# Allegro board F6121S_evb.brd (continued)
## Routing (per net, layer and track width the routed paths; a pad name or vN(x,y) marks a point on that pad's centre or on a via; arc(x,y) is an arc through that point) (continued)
VDD: length 36.4
  TOP w0.305: U3.E5 v2(48.75,41.4) U3.E4 48.5,41.4 ; U3.E3 v2(48.24,41.4) 48.5,41.4 ; 48.5,41.4 v2(48.5,41.13) 48.5,41.13 U3.F4
  TOP w0.508: C6.2 49.35,46.8 50.15,47.6 C20.2 v6(50.93,47.94) ; J16.2 C1.2 C4.2 C3.2 ; C7.2 C5.2
  L2 w0.254: J16.2 26.14,81.34 ; J16.2 25.19,80.39 ; J16.2 26.14,79.44 ; J16.2 27.1,80.39 ; 40.11,54.69 TP6.1 ; TP6.1 38.92,55.88 ; TP6.1 40.11,57.07 ; TP6.1 41.31,55.88 ; J16.8 19.48,80.39 ; J16.8 18.52,81.34 ; J16.8 17.57,80.39 ; J16.8 18.52,79.44 ; 15.03,80.39 J16.10 ; J16.10 16.94,80.39 ; J16.10 15.98,81.34 ; J16.10 15.98,79.44 ; 23.6,79.44 J16.4 ; J16.4 24.56,80.39 ; J16.4 23.6,81.34 ; J16.4 22.65,80.39 ; J16.6 21.06,81.34 ; J16.6 22.02,80.39 ; J16.6 20.11,80.39 ; J16.6 21.06,79.44
  BOTTOM w0.254: 50.1,42.26 C18.2 ; C18.2 50.1,41.5 ; C18.2 50.86,42.26 ; C19.2 46.13,42.11 ; C19.2 45.59,41.57 ; C19.2 46.68,41.57
  vias: v6(41.33,48.84) v6(41.33,48.49) v6(41.33,48.13) v6(41.33,47.78) v6(41.33,47.42) v6(41.33,47.07) v6(41.33,46.71) v6(41.69,48.84) v6(41.69,48.49) v6(41.69,48.13) v6(41.69,47.78) v6(41.69,47.42) v6(41.69,47.07) v6(41.69,46.71) v6(42.05,48.84) v6(42.05,48.49) v6(42.05,48.13) v6(42.05,47.78) v6(42.05,47.42) v6(42.05,47.07) v6(42.05,46.71) v6(42.4,48.84) v6(42.4,48.49) v6(42.4,48.13) v6(42.4,47.78) v6(42.4,47.42) v6(42.4,47.07) v6(42.4,46.71) v6(42.76,48.84) v6(42.76,48.49) v6(42.76,48.13) v6(42.76,47.78) v6(42.76,47.42) v6(42.76,47.07) v6(42.76,46.71) v6(43.11,48.82) v6(43.11,48.46) v6(43.11,48.11) v6(43.11,47.75) v6(43.11,47.4) v6(43.11,47.04) v6(43.11,46.69) v6(43.47,48.82) v6(43.47,48.46) v6(43.47,48.11) v6(43.47,47.75) v6(43.47,47.4) v6(43.47,47.04) v6(43.47,46.69) v6(44.94,46.94) v6(45.22,46.66) v6(45.63,46.81) v6(46,46.95) v6(46.32,46.65) v6(49.11,46.96) v6(49.41,46.66) v6(50,48.06) v6(50.3,47.8) v6(50.71,47.04) v6(50.71,46.69) v6(51.09,49.17) v6(51.09,48.82) v6(51.09,48.46) v6(51.06,47.4) v6(51.06,47.04) v6(51.06,46.69) v6(51.44,49.17) v6(51.44,48.82) v6(51.44,48.46) v6(51.44,48.11) v6(51.44,47.75) v6(51.42,47.4) v6(51.42,47.04) v6(51.42,46.69) v6(51.8,49.17) v6(51.8,48.82) v6(51.8,48.46) v6(51.8,48.08) v6(51.8,47.73) v6(51.77,47.37) v6(51.77,47.02) v6(51.77,46.66) v6(52.13,47.4) v6(52.13,47.04) v6(52.13,46.69) v6(52.15,49.17) v6(52.15,48.82) v6(52.15,48.46) v6(52.15,48.11) v6(52.15,47.75)
VDD_CREG: length 51.8
  TOP w0.305: TP4.1 47.23,53.85 R20.2
  TOP w0.508: J15.3 J14.1 J13.1 J12.1 40.1,77.99 C8.2 37.69,77.98 J11.3
  BOTTOM w0.508: J11.3 35.87,65.2 TP4.1
ADD1: length 59.4
  BOTTOM w0.127: v6(49,40.4) 47.69,39.09 40.39,39.09 30.08,49.4 30.08,78.41 30.89,79.22 34.58,79.22 J11.2
ADD2: length 70.2
  BOTTOM w0.127: v6(49,40.9) 49.41,40.49 49.41,39.98 46.9,37.47 41.27,37.47 29.56,49.18 29.56,81.14 30.23,81.81 38.82,81.81 J12.2
ADD3: length 46.4
  BOTTOM w0.127: v6(49,41.9) 48.4,42.5 48.4,74.8 50.1,76.5 50.1,80.9 49.28,81.71 45.63,81.71 J13.2
ADD4: length 39.4
  BOTTOM w0.127: J14.2 47.48,79.25 47.48,76.12 48,75.61 v6(48,41.9)
ADD5: length 40.9
  L3 w0.127: v6(48.74,49) 47.98,49 47.55,48.57 47.55,46.58 48,46.13 v3(48,42.4)
  BOTTOM w0.127: J15.2 50.51,78.22 50.51,76.28 48.74,74.51 v6(48.74,49)
CREG: length 6.2
  TOP w0.254: U3.C4 v4(48.5,42.14) U3.D4
  TOP w0.305: R20.1 48.2,46.7 v3(48.24,46.66)
  L3 w0.305: v4(48.5,42.14) 48.5,46.41 v3(48.24,46.66)
CSB: length 55.8
  TOP w0.127: v1(69.58,76.78) R12.2 R13.2 ; U3.B4 v5(48.24,42.91)
  TOP w0.254: U3.B4 U3.B3
  L2 w0.127: v5(48.24,42.91) 48.24,43.15 50.83,45.74 53.16,45.74 53.7,46.29 53.7,49.53 52.74,50.5 52.74,72.95 57.67,77.88 68.48,77.88 v1(69.58,76.78)
F2232H_CSB: length 2.6
  TOP w0.127: J22.12 69.58,78.99 R12.1
F2232H_RESET: length 2
  TOP w0.127: R10.1 J22.8
F2232H_SCLK: length 2
  TOP w0.127: R14.1 J22.16
RESET: length 52.8
  TOP w0.127: U3.A3 48,43.72 50.5,46.23 53.96,46.23 55.08,47.35 55.08,54.25 63.3,62.48 v6(63.3,76.02) ; R11.2 R10.2 v6(73.13,76.84)
  BOTTOM w0.127: v6(73.13,76.84) 72.32,76.02 v6(63.3,76.02)
RF1: length 46.2
  L2 w0.203: v1(47,42.9) 45.17,42.9 arc(42.8,43.37) 40.79,44.72 19.22,66.28 arc(18.08,67.04) 16.74,67.31 v1(10.47,67.31)
RF2: length 46.2
  L2 w0.203: v1(3.5,50.04) 25.74,50.04 arc(28.17,49.55) 30.23,48.18 33.89,44.51 arc(36.78,42.58) 40.19,41.9 v1(47,41.9)
RF3: length 46.2
  L2 w0.203: v1(3.5,32.77) 25.74,32.77 arc(28.17,33.25) 30.23,34.63 33.89,38.29 arc(36.78,40.22) 40.19,40.9 v1(47,40.9)
RF4: length 46.2
  L2 w0.203: v1(47,39.9) 45.17,39.9 arc(42.8,39.43) 40.79,38.09 19.22,16.52 arc(18.08,15.76) 16.74,15.49 v1(10.47,15.49)
RF5: length 46.2
  L2 w0.203: v1(50,39.9) 51.83,39.9 arc(54.2,39.43) 56.2,38.09 77.77,16.52 arc(78.91,15.76) 80.25,15.49 v1(86.52,15.49)
RF6: length 46.2
  L2 w0.203: v1(93.49,32.77) 71.26,32.77 arc(68.83,33.25) 66.77,34.63 63.1,38.29 arc(60.21,40.22) 56.8,40.9 v1(50,40.9)
RF7: length 46.2
  L2 w0.203: v1(93.49,50.04) 71.26,50.04 arc(68.83,49.55) 66.77,48.18 63.1,44.51 arc(60.21,42.58) 56.8,41.9 v1(50,41.9)
RF8: length 46.2
  L2 w0.203: v1(86.52,67.31) 80.25,67.31 arc(78.91,67.04) 77.77,66.28 56.2,44.72 arc(54.2,43.37) 51.83,42.9 v1(50,42.9)
SCLK: length 43.5
  TOP w0.127: R14.2 R15.2 63.99,62.33 55.61,53.95 55.61,47.37 54.16,45.92 50.71,45.92 48.5,43.71 U3.A4
SDI: length 43.1
  TOP w0.127: R17.2 R16.2 v6(59.42,76.82)
  TOP w0.254: U3.B5 v5(49,42.66) U3.C5
  L2 w0.127: v6(59.42,76.82) 58.36,76.82 53.37,71.83 53.37,50.62 53.96,50.04 53.96,46.1 53.32,45.47 50.99,45.47 49,43.48 v5(49,42.66)
SDO: length 43.2
  TOP w0.127: R18.2 66.28,75.74 64.65,74.12 64.65,62.18 56.12,53.64 56.12,47.37 54.34,45.59 50.88,45.59 49,43.71 U3.A5
TRIG: length 15.7
  TOP w0.203: 76.23,75.39 76.23,73.66 72.19,69.62 69.35,69.62 J30.1
  TOP w0.216: J22.6 76.23,79.96 76.23,75.39
N397655: length 39.7
  L2 w0.203: v1(58.66,3.5) 58.66,24.41 arc(58.43,25.54) 57.79,26.49 49.68,34.61 arc(49.17,35.36) 49,36.25 v1(49,39.4)
N397670: length 39.7
  L2 w0.203: v1(38.34,3.5) 38.34,24.41 arc(38.56,25.54) 39.2,26.49 47.32,34.61 arc(47.82,35.36) 48,36.25 v1(48,39.4)
N472884: length 1
  TOP w0.127: R11.1 75.14,78.52 C12.2
N475952: length 2.4
  TOP w0.127: J22.18 59.42,79.5 R16.1
N485360: length 3.3
  TOP w0.127: R19.2 66.3,78.55 R18.1 66.28,79.76 J22.14
N489259: length 2.6
  TOP w0.254: R21.1 31.52,80.56 J23.1
N510107: length 1
  TOP w0.127: C14.2 70.62,78.55 R13.1
N511327: length 1
  TOP w0.127: C17.2 68.11,77.46 R19.1
N512531: length 1
  TOP w0.127: R15.1 64.02,78.55 C15.2
N513256: length 1
  TOP w0.127: R17.1 61.43,78.52 C16.2
N546379: length 50.5
  TOP w0.254: U3.G3 v2(48,40.65) U3.F3
  BOTTOM w0.254: v2(48,40.65) 46.85,39.5 40.8,39.5 31.48,48.83 J23.2
N558773: length 1.2
  TOP w0.254: C20.1 50.15,50.13 R26.2

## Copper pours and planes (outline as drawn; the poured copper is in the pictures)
GND on TOP: 93.78,50.34 96.1,50.34 96.99,50.54 96.99,56.39 89.53,56.39 89.53,43.69 96.99,43.69 96.99,49.54 96.1,49.73 93.78,49.73 93.69,49.67 93.59,49.63 93.48,49.62 93.37,49.63 93.27,49.68 93.19,49.74 93.12,49.83 93.08,49.93 93.07,50.04 93.08,50.15 93.12,50.25 93.19,50.33 93.27,50.4 93.37,50.44 93.48,50.46 93.59,50.45 93.69,50.41
GND on TOP: 86.81,67.61 89.14,67.61 90.03,67.81 90.03,73.66 82.56,73.66 82.56,60.96 90.03,60.96 90.03,66.81 89.14,67.01 86.81,67.01 86.72,66.94 86.62,66.9 86.51,66.89 86.41,66.91 86.31,66.95 86.22,67.02 86.16,67.1 86.12,67.2 86.1,67.31 86.12,67.42 86.16,67.52 86.22,67.6 86.31,67.67 86.41,67.71 86.51,67.73 86.62,67.72 86.72,67.68
GND on TOP: 58.96,3.22 58.96,0.89 59.15,0 65.01,0 65.01,7.47 52.31,7.47 52.31,0 58.16,0 58.35,0.89 58.35,3.22 58.29,3.31 58.25,3.41 58.24,3.51 58.25,3.62 58.3,3.72 58.36,3.8 58.45,3.87 58.55,3.91 58.66,3.92 58.76,3.91 58.86,3.87 58.95,3.8 59.02,3.72 59.06,3.62 59.08,3.51 59.06,3.41 59.03,3.31
GND on TOP: 10.19,67.01 7.86,67.01 6.97,66.81 6.97,60.96 14.44,60.96 14.44,73.66 6.97,73.66 6.97,67.81 7.86,67.61 10.19,67.61 10.27,67.68 10.37,67.72 10.48,67.73 10.59,67.71 10.69,67.67 10.77,67.6 10.84,67.52 10.88,67.42 10.89,67.31 10.88,67.2 10.84,67.1 10.77,67.02 10.69,66.95 10.59,66.91 10.48,66.89 10.37,66.9 10.27,66.94
GND on TOP: 86.81,15.8 89.14,15.8 90.03,15.99 90.03,21.84 82.56,21.84 82.56,9.14 90.03,9.14 90.03,15 89.14,15.19 86.81,15.19 86.72,15.13 86.62,15.09 86.51,15.07 86.41,15.09 86.31,15.13 86.22,15.2 86.16,15.29 86.12,15.39 86.1,15.49 86.12,15.6 86.16,15.7 86.22,15.79 86.31,15.85 86.41,15.9 86.51,15.91 86.62,15.9 86.72,15.86
GND on TOP: 6.97,0 6.97,9.34 14.39,9.34 14.39,21.64 6.97,21.64 6.97,25.41 0,25.41 0,26.58 7.46,26.58 7.42,26.58 7.41,38.9 0,38.9 0,43.87 7.4,43.87 7.38,56.19 0,56.2 0,57.39 6.97,57.39 6.97,61.15 14.4,61.15 14.4,73.46 6.97,73.46 6.97,86.08 90.03,86.08 90.03,73.44 82.61,73.44 82.61,61.12 90.03,61.13 90.03,57.39 96.99,57.39 96.99,56.21 89.58,56.21 89.57,43.86 96.99,43.86 96.99,38.9 89.58,38.9 89.57,26.62 96.99,26.62 96.99,25.41 90.03,25.41 90.03,21.64 82.61,21.64 82.61,9.33 90.03,9.33 90.02,0 64.77,0 64.77,7.38 52.54,7.38 52.52,0 44.48,0 44.48,7.43 32.18,7.4 32.16,0 ; 2 cut-outs
GND on TOP: 3.22,49.73 0.89,49.73 0,49.54 0,43.69 7.47,43.69 7.47,56.39 0,56.39 0,50.54 0.89,50.34 3.22,50.34 3.31,50.41 3.41,50.45 3.51,50.46 3.62,50.44 3.72,50.4 3.8,50.33 3.87,50.25 3.91,50.15 3.92,50.04 3.91,49.93 3.87,49.83 3.8,49.74 3.72,49.68 3.62,49.63 3.51,49.62 3.41,49.63 3.31,49.67
GND on TOP: 93.78,33.07 96.1,33.07 96.99,33.26 96.99,39.12 89.53,39.12 89.53,26.42 96.99,26.42 96.99,32.27 96.1,32.46 93.78,32.46 93.69,32.4 93.59,32.36 93.48,32.35 93.37,32.36 93.27,32.41 93.19,32.47 93.12,32.56 93.08,32.66 93.07,32.77 93.08,32.87 93.12,32.97 93.19,33.06 93.27,33.13 93.37,33.17 93.48,33.19 93.59,33.17 93.69,33.13
GND on TOP: 10.19,15.19 7.86,15.19 6.97,15 6.97,9.14 14.44,9.14 14.44,21.84 6.97,21.84 6.97,15.99 7.86,15.8 10.19,15.8 10.27,15.86 10.37,15.9 10.48,15.91 10.59,15.9 10.69,15.85 10.77,15.79 10.84,15.7 10.88,15.6 10.89,15.49 10.88,15.39 10.84,15.29 10.77,15.2 10.69,15.13 10.59,15.09 10.48,15.07 10.37,15.09 10.27,15.13
GND on TOP: 3.22,32.46 0.89,32.46 0,32.27 0,26.42 7.47,26.42 7.47,39.12 0,39.12 0,33.26 0.89,33.07 3.22,33.07 3.31,33.13 3.41,33.17 3.51,33.19 3.62,33.17 3.72,33.13 3.8,33.06 3.87,32.97 3.91,32.87 3.92,32.77 3.91,32.66 3.87,32.56 3.8,32.47 3.72,32.41 3.62,32.36 3.51,32.35 3.41,32.36 3.31,32.4
GND on TOP: 38.64,3.22 38.64,0.89 38.83,0 44.69,0 44.69,7.47 31.99,7.47 31.99,0 37.84,0 38.03,0.89 38.03,3.22 37.97,3.31 37.93,3.41 37.92,3.51 37.93,3.62 37.98,3.72 38.04,3.8 38.13,3.87 38.23,3.91 38.34,3.92 38.44,3.91 38.54,3.87 38.63,3.8 38.7,3.72 38.74,3.62 38.76,3.51 38.74,3.41 38.71,3.31
GND on BOTTOM, L3: 6.97,25.41 0,25.41 0,57.39 6.97,57.39 6.97,86.08 90.03,86.08 90.03,57.39 96.99,57.39 96.99,25.41 90.03,25.41 90.03,0 6.97,0
GND on L2: 6.97,21.84 14.44,21.84 14.44,15.82 10.73,15.82 10.64,15.88 10.53,15.91 10.42,15.91 10.31,15.88 10.27,15.86 10.22,15.82 10.1,15.68 10.06,15.49 10.1,15.31 10.22,15.16 10.27,15.13 10.31,15.11 10.42,15.08 10.53,15.08 10.64,15.11 10.73,15.16 14.44,15.16 14.44,9.14 6.97,9.14
GND on L2: 82.56,21.84 90.03,21.84 90.03,9.14 82.56,9.14 82.56,15.16 86.26,15.16 86.31,15.13 86.41,15.09 86.63,15.09 86.73,15.13 86.77,15.16 86.9,15.31 86.94,15.49 86.9,15.68 86.77,15.83 86.73,15.86 86.63,15.9 86.41,15.9 86.31,15.85 86.26,15.82 82.56,15.82
GND on L2: 38.67,7.47 44.69,7.47 44.69,0 31.99,0 31.99,7.47 38.01,7.47 38.01,3.76 37.95,3.67 37.92,3.56 37.92,3.45 37.95,3.35 38,3.25 38.01,3.25 38.15,3.13 38.34,3.09 38.52,3.13 38.66,3.25 38.67,3.25 38.72,3.35 38.75,3.45 38.75,3.56 38.72,3.67 38.67,3.76
GND on L2: 6.97,73.66 14.44,73.66 14.44,67.64 10.73,67.64 10.68,67.67 10.58,67.71 10.37,67.71 10.26,67.67 10.22,67.64 10.1,67.5 10.05,67.31 10.1,67.12 10.22,66.98 10.26,66.95 10.37,66.91 10.58,66.91 10.68,66.95 10.73,66.98 14.44,66.98 14.44,60.96 6.97,60.96
GND on L2: 6.97,25.41 0,25.41 0,26.58 7.35,26.59 7.35,38.88 0,38.95 0,43.69 7.48,43.69 7.48,56.21 0,56.21 0,57.39 6.97,57.39 6.97,61.21 14.33,61.21 14.33,73.47 6.97,73.47 6.97,86.08 90.03,86.08 90.03,73.66 82.79,73.66 82.79,60.96 90.03,60.96 90.03,57.39 96.99,57.39 96.99,56.21 89.55,56.21 89.55,43.69 96.99,43.69 96.99,38.94 89.55,38.94 89.55,26.58 96.99,26.58 96.99,25.41 90.03,25.41 90.03,21.84 82.79,21.84 82.79,9.14 90.03,9.14 90.03,0 64.75,0 64.75,7.37 52.43,7.37 52.43,0 44.43,0 44.43,7.37 32.24,7.37 32.24,0 6.97,0 6.97,9.4 14.33,9.37 14.33,21.59 6.97,21.59 ; 10 cut-outs
GND on L2: 89.48,56.39 96.99,56.39 96.99,43.69 89.53,43.69 89.53,49.71 93.23,49.71 93.28,49.68 93.38,49.64 93.6,49.63 93.7,49.68 93.86,49.85 93.91,50.04 93.86,50.22 93.7,50.4 93.6,50.44 93.38,50.44 93.28,50.4 93.23,50.37 89.48,50.37
GND on L2: 89.53,39.12 96.99,39.12 96.99,26.42 89.53,26.42 89.53,32.44 93.23,32.44 93.28,32.41 93.38,32.36 93.6,32.36 93.7,32.4 93.74,32.43 93.86,32.58 93.91,32.77 93.86,32.95 93.74,33.1 93.7,33.13 93.6,33.17 93.38,33.17 93.28,33.13 93.23,33.1 89.53,33.1
GND on L2: 82.56,73.66 90.03,73.66 90.03,60.96 82.56,60.96 82.56,66.98 86.26,66.98 86.31,66.95 86.41,66.91 86.63,66.91 86.73,66.95 86.77,66.98 86.9,67.12 86.94,67.31 86.9,67.5 86.77,67.64 86.73,67.67 86.63,67.71 86.41,67.71 86.31,67.67 86.26,67.64 82.56,67.64
GND on L2: 0,39.12 7.47,39.12 7.47,33.1 3.76,33.1 3.67,33.15 3.56,33.18 3.45,33.18 3.35,33.15 3.3,33.13 3.25,33.1 3.13,32.95 3.09,32.77 3.13,32.58 3.25,32.44 3.3,32.4 3.35,32.38 3.45,32.35 3.56,32.35 3.67,32.38 3.76,32.44 7.47,32.44 7.47,26.42 0,26.42
GND on L2: 0,56.39 7.49,56.39 7.49,50.37 3.76,50.37 3.72,50.4 3.62,50.44 3.4,50.44 3.3,50.4 3.25,50.37 3.13,50.22 3.09,50.04 3.13,49.85 3.25,49.71 3.3,49.68 3.4,49.63 3.62,49.64 3.72,49.68 3.76,49.71 7.5,49.71 7.5,43.69 0,43.69
GND on L2: 58.99,7.47 65.01,7.47 65.01,0 52.31,0 52.31,7.47 58.33,7.47 58.33,3.76 58.27,3.67 58.25,3.62 58.24,3.5 58.25,3.4 58.29,3.3 58.33,3.25 58.47,3.13 58.66,3.09 58.84,3.13 58.99,3.25 59.02,3.3 59.06,3.4 59.07,3.5 59.06,3.62 59.04,3.67 58.99,3.76
VDD on BOTTOM: 48.73,49.39 52.56,49.39 52.56,43.43 50.33,41.2 50.33,40.56 49.72,40.56 49.18,41.2 48.86,41.2 48.69,41.02 48.7,40.69 46.74,40.69 46.74,41.22 42.55,41.22 41.12,42.65 41.09,49.35 47.63,49.35 47.63,41.81 47.85,41.59 49.14,41.58 49.31,41.74 49.31,42.14 48.73,42.72
VDD on L2: 27.9,81.66 13.98,81.66 13.98,77.51 18.04,77.55 18.04,71.48 35.42,54.1 41.11,54.08 41.11,46.36 52.56,46.36 52.56,49.53 48.09,49.53 48.09,63.7 27.9,77.19
RF1 on TOP (solid shape): 10.51,67.52 10.56,67.51 10.61,67.48 10.65,67.44 10.67,67.39 10.69,67.34 10.69,67.28 10.67,67.23 10.65,67.18 10.61,67.14 10.56,67.11 10.51,67.1 10.45,67.1 10.4,67.11 10.35,67.13 6.97,67.13 6.97,67.49 10.35,67.49 10.4,67.51 10.45,67.52
RF1 on L2 (solid shape): 10.52,67.45 10.56,67.44 10.59,67.41 14.44,67.41 14.44,67.21 10.59,67.21 10.56,67.18 10.52,67.17 10.49,67.16 10.45,67.16 10.41,67.17 10.38,67.19 10.35,67.22 10.33,67.25 10.32,67.29 10.32,67.33 10.33,67.37 10.35,67.4 10.38,67.43 10.41,67.45 10.45,67.46 10.49,67.46
RF2 on TOP (solid shape): 3.54,50.25 3.59,50.24 3.64,50.21 3.68,50.17 3.71,50.12 3.72,50.07 3.72,50.01 3.71,49.96 3.68,49.91 3.64,49.87 3.59,49.84 3.54,49.82 3.49,49.82 3.43,49.84 3.38,49.86 0,49.86 0,50.22 3.38,50.22 3.43,50.24 3.49,50.25
RF2 on L2 (solid shape): 3.55,50.18 3.59,50.16 3.62,50.14 7.47,50.14 7.47,49.94 3.62,49.94 3.59,49.91 3.55,49.89 3.52,49.89 3.48,49.89 3.44,49.9 3.41,49.92 3.38,49.95 3.36,49.98 3.35,50.02 3.35,50.06 3.36,50.09 3.38,50.13 3.41,50.16 3.44,50.18 3.48,50.19 3.52,50.19
RF3 on TOP (solid shape): 3.54,32.98 3.59,32.96 3.64,32.93 3.68,32.89 3.71,32.85 3.72,32.79 3.72,32.74 3.71,32.69 3.68,32.64 3.64,32.6 3.59,32.57 3.54,32.55 3.49,32.55 3.43,32.56 3.38,32.59 0,32.59 0,32.94 3.38,32.94 3.43,32.97 3.49,32.98
RF3 on L2 (solid shape): 3.55,32.91 3.59,32.89 3.62,32.87 7.47,32.87 7.47,32.66 3.62,32.66 3.59,32.64 3.55,32.62 3.52,32.61 3.48,32.62 3.44,32.63 3.41,32.65 3.38,32.68 3.36,32.71 3.35,32.75 3.35,32.79 3.36,32.82 3.38,32.86 3.41,32.88 3.44,32.9 3.48,32.92 3.52,32.92
RF4 on TOP (solid shape): 10.51,15.71 10.56,15.69 10.61,15.66 10.65,15.62 10.67,15.57 10.69,15.52 10.69,15.47 10.67,15.41 10.65,15.37 10.61,15.33 10.56,15.3 10.51,15.28 10.45,15.28 10.4,15.29 10.35,15.32 6.97,15.32 6.97,15.67 10.35,15.67 10.4,15.7 10.45,15.71
RF4 on L2 (solid shape): 10.52,15.64 10.56,15.62 10.59,15.6 14.44,15.6 14.44,15.39 10.59,15.39 10.56,15.37 10.52,15.35 10.49,15.34 10.45,15.34 10.41,15.36 10.38,15.38 10.35,15.4 10.33,15.44 10.32,15.47 10.32,15.51 10.33,15.55 10.35,15.58 10.38,15.61 10.41,15.63 10.45,15.64 10.49,15.65
RF5 on TOP (solid shape): 86.59,15.7 86.64,15.67 90.03,15.67 90.03,15.32 86.64,15.32 86.59,15.29 86.54,15.28 86.49,15.28 86.43,15.3 86.39,15.33 86.35,15.37 86.32,15.41 86.31,15.47 86.31,15.52 86.32,15.57 86.35,15.62 86.39,15.66 86.43,15.69 86.49,15.71 86.54,15.71
RF5 on L2 (solid shape): 86.55,15.64 86.58,15.63 86.62,15.61 86.64,15.58 86.66,15.55 86.67,15.51 86.67,15.47 86.66,15.44 86.64,15.4 86.62,15.38 86.58,15.36 86.55,15.34 86.51,15.34 86.47,15.35 86.44,15.37 86.41,15.39 82.56,15.39 82.56,15.6 86.41,15.6 86.44,15.62 86.47,15.64 86.51,15.65
RF6 on TOP (solid shape): 93.56,32.97 93.61,32.94 96.99,32.94 96.99,32.59 93.61,32.59 93.56,32.56 93.51,32.55 93.45,32.55 93.4,32.57 93.35,32.6 93.32,32.64 93.29,32.69 93.27,32.74 93.27,32.79 93.29,32.85 93.32,32.89 93.35,32.93 93.4,32.96 93.45,32.98 93.51,32.98
RF6 on L2 (solid shape): 93.51,32.92 93.55,32.9 93.58,32.88 93.61,32.86 93.63,32.82 93.64,32.79 93.64,32.75 93.63,32.71 93.61,32.68 93.58,32.65 93.55,32.63 93.51,32.62 93.48,32.61 93.44,32.62 93.4,32.64 93.37,32.66 89.53,32.66 89.53,32.87 93.37,32.87 93.4,32.89 93.44,32.91 93.48,32.92
RF7 on TOP (solid shape): 93.56,50.24 93.61,50.22 96.99,50.22 96.99,49.86 93.61,49.86 93.56,49.84 93.51,49.82 93.45,49.82 93.4,49.84 93.35,49.87 93.32,49.91 93.29,49.96 93.27,50.01 93.27,50.07 93.29,50.12 93.32,50.17 93.35,50.21 93.4,50.24 93.45,50.25 93.51,50.25
RF7 on L2 (solid shape): 93.51,50.19 93.55,50.18 93.58,50.16 93.61,50.13 93.63,50.09 93.64,50.06 93.64,50.02 93.63,49.98 93.61,49.95 93.58,49.92 93.55,49.9 93.51,49.89 93.48,49.89 93.44,49.89 93.4,49.91 93.37,49.94 89.53,49.94 89.53,50.14 93.37,50.14 93.4,50.16 93.44,50.18 93.48,50.19
RF8 on TOP (solid shape): 86.59,67.51 86.64,67.49 90.03,67.49 90.03,67.13 86.64,67.13 86.59,67.11 86.54,67.1 86.49,67.1 86.43,67.11 86.39,67.14 86.35,67.18 86.32,67.23 86.31,67.28 86.31,67.34 86.32,67.39 86.35,67.44 86.39,67.48 86.43,67.51 86.49,67.52 86.54,67.52
RF8 on L2 (solid shape): 86.55,67.46 86.58,67.45 86.62,67.43 86.64,67.4 86.66,67.37 86.67,67.33 86.67,67.29 86.66,67.25 86.64,67.22 86.62,67.19 86.58,67.17 86.55,67.16 86.51,67.16 86.47,67.17 86.44,67.18 86.41,67.21 82.56,67.21 82.56,67.41 86.41,67.41 86.44,67.44 86.47,67.45 86.51,67.46
N397655 on TOP (solid shape): 58.74,3.71 58.79,3.68 58.83,3.64 58.85,3.59 58.87,3.54 58.87,3.49 58.86,3.43 58.83,3.38 58.83,0 58.48,0 58.48,3.38 58.45,3.43 58.44,3.49 58.44,3.54 58.46,3.59 58.49,3.64 58.53,3.68 58.58,3.71 58.63,3.72 58.68,3.72
N397655 on L2 (solid shape): 58.76,3.62 58.78,3.59 58.8,3.55 58.81,3.52 58.81,3.48 58.8,3.44 58.78,3.41 58.75,3.38 58.71,3.36 58.68,3.35 58.64,3.35 58.6,3.36 58.57,3.38 58.54,3.41 58.52,3.44 58.51,3.48 58.5,3.52 58.51,3.55 58.53,3.59 58.56,3.62 58.56,7.47 58.76,7.47
N397670 on TOP (solid shape): 38.42,3.71 38.47,3.68 38.51,3.64 38.53,3.59 38.55,3.54 38.55,3.49 38.54,3.43 38.51,3.38 38.51,0 38.16,0 38.16,3.38 38.13,3.43 38.12,3.49 38.12,3.54 38.14,3.59 38.17,3.64 38.21,3.68 38.26,3.71 38.31,3.72 38.36,3.72
N397670 on L2 (solid shape): 38.44,3.62 38.46,3.59 38.48,3.55 38.49,3.52 38.49,3.48 38.48,3.44 38.46,3.41 38.43,3.38 38.39,3.36 38.36,3.35 38.32,3.35 38.28,3.36 38.25,3.38 38.22,3.41 38.2,3.44 38.19,3.48 38.18,3.52 38.19,3.55 38.21,3.59 38.24,3.62 38.24,7.47 38.44,7.47

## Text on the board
Ref Des/Silkscreen Bottom: GND | SDI | SCLK | SDO | CSB | RESET | TRIG | MODE
Ref Des/Silkscreen Top: VDD | GND | IB | ADD1 | VDD_CREG | ADD2 | ADD3 | ADD4 | ADD5 | TRIG | HWE-F6121S-A | 3/20 | RF2 | RF3 | RF4 | RF1 | RFC1 | RFC2 | RF8 | RF5 | RF7 | RF6
PAGE_OUTLINE: R | REV. | 1140 West Warner Suite, 106 | Tempe, Arizona 85284 | HWE-F6121S | F6121S | A
XSECTION_CHART: STACKUP TABLE | Unit = Mils | # | 1 | 2 | 3 | 4 | NAME | TOP | L2 | L3 | BOTTOM | TYPE | SURFACE | PLANE | DIELECTRIC | CONDUCTOR | MATERIAL | AIR | 0.5_COPPER | MEGTRON6_10_GHZ | 1OZ_COPPER | TOTAL THICKNESS | THICKNESS | 0 | 0.7 | 9 | 1.4 | 10 | 41 | 64.2
User.8: FIGURE | FINISHED_SIZE | 6.0 | DRILL CHART: TOP to L2 | ALL UNITS ARE IN MILS | TOLERANCE_DRILL | +3.0/-3.0 | PLATED | QTY | 389
User.9: FIGURE | FINISHED_SIZE | 6.0 | DRILL CHART: TOP to L3 | ALL UNITS ARE IN MILS | TOLERANCE_DRILL | +3.0/-3.0 | PLATED | QTY | 2574
User.10: FIGURE | FINISHED_SIZE | 6.0 | 40.16 | 45.0 | 65.0 | 129.92 | 80.0 | DRILL CHART: TOP to BOTTOM | ALL UNITS ARE IN MILS | TOLERANCE_DRILL | +3.0/-3.0 | +2.99/-2.99 | +2.0/-2.0 | PLATED | NON-PLATED | QTY | 2841 | 47 | 3 | 1 | 4 | 20
User.11: 11. GROUND SHAPES EXTENDED TO BOARD EDGE ARE INTENTIONAL. | 12. RoHS COMPLAINT. | 13. FILL 6 MIL VIA'S WITH NON-CONDUCTIVE MATERIAL AND CU PLATE. FLAT PADS WITH NO DIMPLES | NOTES: UNLESS OTHERWISE SPECIFIED: | 10. SERIALIZE BOARDS AS FOLLOWS: "S/N YYYYMM##" YEAR, MONTH-NUMBER. | - THE PURCHASE ORDER | - THIS DRAWING | - IPC-6012 SERIES, CURRENT REVISION, CLASS 2. | - IPC-A-600 CURRENT REVISION, CLASS 2. | SHOWN IN CHART REQUIRE 0.001" MINIMUM BARREL PLATING THICHNESS. NOTE | REQUIRED. OUTGASSING NOT PERMITTED. | - IPC-7721 CURRENT REVISION, CLASS 2. | THICKNESS 120-240 MICRO-INCHES. GOLD THICKNESS 3-6 MICRO-INCHES. | 4. SURFACE FINISH: ELECTROLESS NICKEL/IMMERSION GOLD PER IPC-4552. NICKEL | 1. APPLICABLE SPECIFICATIONS AND ORDER OF PRECEDENCE: | 3. PLATING: ADDITIONAL CU PLATE APPROX. 1OZ./5QFT. PLATED THROUGH HOLES AS | CLASS H AND ARTWORK SUPPLIED. ENSURE SOLDERMASK DOES NOT ENCROACH ON SMD LANDS. | COLOR BLUE. | 9. SOLDERABILITY: SOLDERABLITITY TO BE CONFIRMED PER LOT IAW IPC-650. | 6. SILKSCREEN:APPLY NON-CONDUCTIVE/NON-NUTRIENT EPOXY INK PER ARTWORK | REFERENCE STACKUP AND REQUIREMENTS BELOW. FLAMMABILITY RATING 94VO REQUIRED. | SUPPLIED. ENSURE NO LEGEND IS APPLIED OVER SOLDERABLE SURFACES. MARK LOGO | 5. SOLDERMASK: LPI SOLDERMASK SMOBC BOTH SIDES PER IPC-SM-840 CURRENT REVISION. | CU AS NEEDED PER PROCESS AND/OR BOW/TWIST REQUIREMENTS. | IPC-D-356 FORMAT. FINAL PRODUCT TO BE TESTED TRACEABLE TO SAME. | UL RATING AND DATE CODE ON SECONDARY SIDE. | 2. MATERIAL:MEGTRON 6 COPPER THICKNESS, DIELECTRIC ARRANGEMENT AND THICKNESS PER | 7. ARTWORK: BOARD IS DESIGNED TO NOMINAL 5/5 TECNOLOGY. VENDOR MAY ADD OR REMOVE NON-FUCTIONAL | 8. NETLIST TEST: VENDOR TO PROVE TOOLED GERBER FILES AGAINST SUPPLIED NETLIST IN | MANUFACTURING: | IT IS IMPORTANT THAT VIAS | IN THIS AREA TO BE PLATED | FLAT FOR THE IC AND SOCKET | CONNECTOR BODY TO BE FLUSH AGAINST BOARD EDGE. NO AIR GAP'S PERMITTED. | 7. WHEN MOUNTING SMA CONNECTORS ENSURE THAT CONNECTOR PIN IS CENTERED AND FLUSH WITH TRACE. | 6. SOLER TYPE: LEAD FREE. | 5. ASSEMBLE AND SOLDER IN ACCORDANCE TO IPC-610 CLASS II (CURRENT REVISION). | SHIPPING OF THIS ASSEMBLY. | TO THIS A CHAMFERED CONRNER OR AN INDENTED OUTLINE WILL ALSO INDICATE PIN ONE OF | 3. THE FOLLOWING ARE FOR REFERENCE ONLY AND MAY NOT APPEAR ON THE PARTS. | A DEVICE OR CONNECTOR. | COMPONETS WILL BE DISIGNATED AS "NP" OR "SP". | 4. FOR COMPONETS NOT TO BE INSTALLED REFER TO SCHEMATIC AND BILL OF MATERIALS. THESE | PIN  OR CIRCLE WILL INDICATE THE PIN ONE OF A DEVICE OR CONNTECTOR. IN ADDITION | A PLUS SIGN (+) INDICATES THE POSTIVE END OF A POLARIZED CAPACITOR. A SQUARE | ACCORDANCE TO MIL-STD-1686/IPC-610 CLASS II AND III IN HANDLING, STORAGE AND | 2. CAUTION: ELECTRO STATIC DEVICES: THIS ASSEMBLY CONTAINS PARTS SENSITIVE TO | DAMAGE BY ELECTROSTAATIC DISCHARGE (ESD) USE PRECAUTIONARY PROCEDURES IN | 1. FOR SCHEMATIC DIAGRAM PLEASE SEE F5280 28GHZ EVB AFR REVB.OBJ | ASSEMBLY:
